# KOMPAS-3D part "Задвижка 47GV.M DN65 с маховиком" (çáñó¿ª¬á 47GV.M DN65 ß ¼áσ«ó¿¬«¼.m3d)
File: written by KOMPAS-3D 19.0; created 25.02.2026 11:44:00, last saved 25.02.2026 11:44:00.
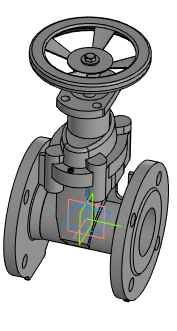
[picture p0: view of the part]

Document properties: Автор: Евгений; Полное имя файла: 47 GV.M DN50\Задвижка 47GV.M DN50 с маховиком.a3d

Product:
- Part/product: Задвижка 47GV.M DN65 с маховиком
    Масса: 15.3455
    Раздел спецификации: Документация
    Форматы листов документа: 2xA3
    source file: 47GV.M DN65\DR.47GVM.050.16.00.000 - Задвижка с обрезиненным клином DN50.spw, 47GV.M DN65\DR.47GVM.050.16.00.000 СБ - Задвижка с обрезиненным клином DN100.cdw
  - Component: Задвижка с обрезиненным клином DN50. Сборочный чертеж  | designation DR.47GVM.050.16.00.000СБ  | pos. 0  | Масса: 10.0548; Раздел спецификации: Документация; Форматы листов документа: 2xA3; source file: 47GV.M DN65\DR.47GVM.050.16.00.000 СБ - Задвижка с обрезиненным клином DN100.cdw
- Part/product: Задвижка 47GV.M DN65 с маховиком  | designation 01
    Масса: 10.055
  - Component [standard]: Болт86g187798  | pos. 17  | Масса: 0.0123; Раздел спецификации: Стандартные изделия; Примечание: См. п.6 ТТ; Рассекать на разрезах: no; additional columns: ГОСТ 7798-70; М8-6gx18
  - Component [standard]: Шайба821695878  | pos. 16
      Материал: Сталь 12Х18Н10Т ГОСТ 5632-2014 (density 1000 kg/m3)
      Масса: 0.000793943
      Раздел спецификации: Стандартные изделия
      Примечание: См. п.6 ТТ
      Рассекать на разрезах: no
      additional columns: ГОСТ 6958-78; A 8.21
  - Component [detail]: Маховик 160  | pos. 20  | Масса: 0.340724; Раздел спецификации: Прочие изделия; source file: 47GV.M DN65\Маховик 160.m3d
  - Component [detail]: Шпиндель  | pos. 5  | Материал: Сталь 20Х13 ГОСТ 5632-2014 (density 7670 kg/m3); Масса: 0.101759; Раздел спецификации: Детали; source file: 47GV.M DN50\DR.47GVM.050.16.00.003 - Шпиндель.cdw, 47GV.M DN65\DR.47GVM.050.16.00.003 - Шпиндель.cdw, 47GV.M DN65\Шпиндель 47GV.M DN50.m3d
  - Component [detail]: Крышка DN65  | pos. 4  | Материал: ВЧ50 ГОСТ 7293-85 (density 7200 kg/m3); Масса: 1.87183; Раздел спецификации: Детали; Форматы листов документа: 2xA3; source file: 47GV.M DN65\DR.47GVM.050.16.00.002 - Крышка.cdw, 47GV.M DN65\DR.47GVM.065.16.00.002 - Крышка.cdw, 47GV.M DN65\Крышка 47GV.M DN50.m3d
  - Component [assembly]: Клин с направляющими  | designation DR.47GVM.050.16.01.000  | pos. 4  | Раздел спецификации: Сборочные единицы; Форматы листов документа: A4; source file: 47GV.M DN65\DR.47GVM.050.16.01.000  - Клин с направляющими.a3d, 47GV.M DN65\DR.47GVM.050.16.01.000  - Клин с направляющими.spw, 47GV.M DN65\DR.47GVM.050.16.01.000  СБ - Клин с направляющими.cdw
  - Component [detail]: Корпус  | designation DR.47GVM.065.16.00.001  | pos. 3  | Материал: ВЧ50 ГОСТ 7293-85 (density 7200 kg/m3); Масса: 11.3996; Раздел спецификации: Детали; Форматы листов документа: 2xA3; source file: 47GV.M DN65\DR.47GVM.050.16.00.001 - Корпус.cdw, 47GV.M DN65\Корпус 47GV.M DN50.m3d

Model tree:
1. Операция без истории:1

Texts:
  Точка начала. Х
  Точка начала. Y
  Точка начала. Z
